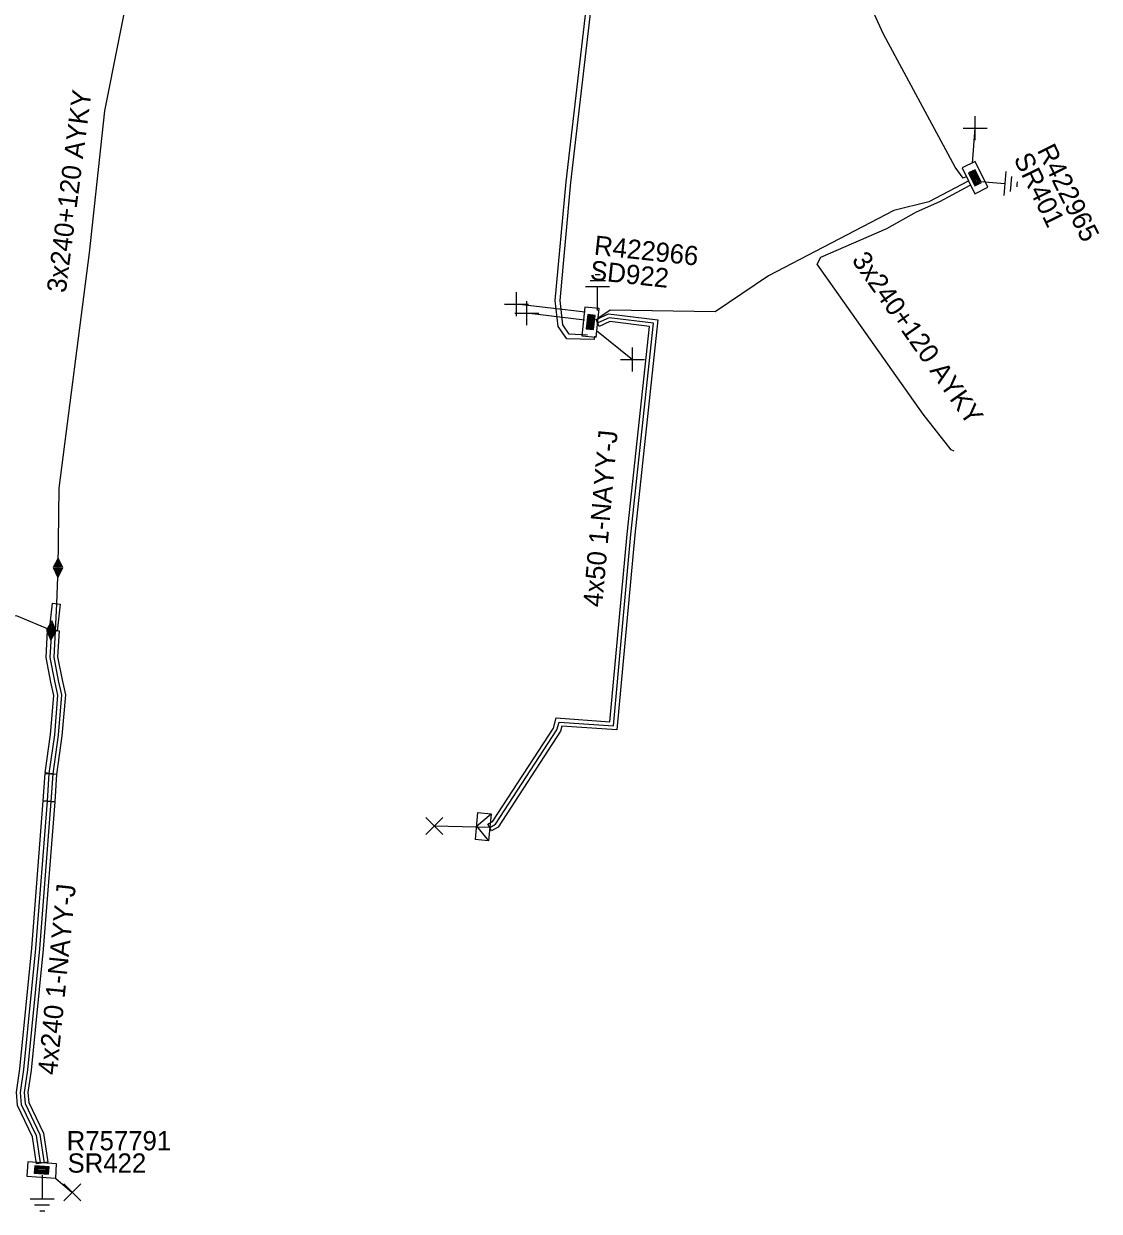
# Model space of a CAD drawing. Extents: x -540466 to -537383, y -1184038 to -1179972.
# Drawn here: x -537936.6 to -537880.7, y -1180884.6 to -1180822.8 of the extents above; entities that cross this region are included whole.
import ezdxf

# ---------------------------------------------------------------- set-up
doc = ezdxf.new("R2010")
doc.units = 0
for name, color, linetype in [('Vrstva 1', 7, 'Continuous'), ('Vrstva 14', 7, 'Continuous'), ('Vrstva 15', 7, 'Continuous'), ('Vrstva 19', 7, 'Continuous'), ('Vrstva 20', 7, 'Continuous'), ('Vrstva 28', 7, 'Continuous'), ('Vrstva 29', 7, 'Continuous'), ('Vrstva 30', 7, 'Continuous'), ('Vrstva 31', 7, 'Continuous'), ('Vrstva 34', 7, 'Continuous'), ('Vrstva 4', 7, 'Continuous'), ('Vrstva 5', 7, 'Continuous'), ('Vrstva 59', 7, 'Continuous'), ('Vrstva 6', 7, 'Continuous'), ('Vrstva 8', 7, 'Continuous'), ('Vrstva 9', 7, 'Continuous')]:
    doc.layers.add(name, color=color, linetype=linetype)

# ---------------------------------------------------------------- blocks, each defined once
blk = doc.blocks.new('NN870')
at = {"layer": 'Vrstva 4'}
for points in [[(0, -0.251), (0.5, 0.001), (0, 0.249), (-0.5, 0.001), (0, -0.251)], [(0.37, -0.003), (0, 0.186), (-0.362, 0.001), (0, -0.188), (0.37, -0.003)], [(0.245, -0.003), (0, 0.123), (-0.252, -0.003), (0, -0.125), (0.245, -0.003)], [(0.122, -0.003), (0, 0.06), (-0.13, -0.003), (0, -0.062), (0.122, -0.003)]]:
    blk.add_lwpolyline(points, dxfattribs=at)
blk = doc.blocks.new('NN800')
at = {"layer": 'Vrstva 1'}
for points in [[(-0.442, 0.442), (0.442, -0.442)], [(-0.442, -0.442), (0.442, 0.442)]]:
    blk.add_lwpolyline(points, dxfattribs=at)
blk = doc.blocks.new('NN620')
at = {"layer": 'Vrstva 8'}
for points in [[(0.752, 0.004), (-0.748, 0.004)], [(-0.748, 0.004), (-0.748, -0.746)], [(0.752, -0.746), (0.752, 0.004)], [(0.368, -0.18), (-0.376, -0.18)], [(-0.376, -0.18), (-0.376, -0.558)], [(-0.376, -0.558), (0.368, -0.558)], [(0.321, -0.227), (-0.329, -0.227)], [(-0.329, -0.227), (-0.329, -0.51)], [(-0.329, -0.51), (0.321, -0.51)], [(0.274, -0.274), (-0.281, -0.274)], [(-0.281, -0.274), (-0.281, -0.463)], [(-0.281, -0.463), (0.274, -0.463)], [(0.227, -0.321), (-0.234, -0.321)], [(-0.234, -0.321), (-0.234, -0.416)], [(-0.234, -0.416), (0.227, -0.416)], [(-0.193, -0.369), (0.185, -0.369)], [(0.227, -0.416), (0.227, -0.321)], [(0.274, -0.463), (0.274, -0.274)], [(0.321, -0.51), (0.321, -0.227)], [(0.368, -0.558), (0.368, -0.18)], [(-0.748, -0.746), (0.752, -0.746)]]:
    blk.add_lwpolyline(points, dxfattribs=at)
blk = doc.blocks.new('NN630')
at = {"layer": 'Vrstva 9'}
for points in [[(-0.003, -0.7), (-0.703, 0)], [(-0.703, -0.7), (-0.703, 0), (0.697, 0), (0.697, -0.7)], [(-0.003, -0.7), (0.697, 0)], [(-0.703, -0.7), (0.697, -0.7)]]:
    blk.add_lwpolyline(points, dxfattribs=at)
blk = doc.blocks.new('NN810')
at = {"layer": 'Vrstva 14'}
for points in [[(0.004, -0.64), (0.004, -1.89)], [(0.629, -1.89), (-0.621, -1.89)], [(0.388, -2.2), (-0.399, -2.2)], [(0.004, -2.515), (-0.124, -2.515)], [(0.137, -2.515), (0.004, -2.515)]]:
    blk.add_lwpolyline(points, dxfattribs=at)

msp = doc.modelspace()

# ---------------------------------------------------------------- linework, layer by layer
at = {"layer": 'Vrstva 20'}
for points in [[(-537912.485, -1180864.435), (-537912.228, -1180864.289), (-537909.081, -1180859.446), (-537908.936, -1180858.918), (-537906.138, -1180859.116), (-537905.246, -1180849.359), (-537904.087, -1180838.573), (-537906.146, -1180838.314), (-537906.695, -1180838.561), (-537906.859, -1180838.197), (-537906.208, -1180837.904), (-537903.647, -1180838.225), (-537904.848, -1180849.399), (-537905.775, -1180859.542), (-537908.637, -1180859.34), (-537908.712, -1180859.612), (-537911.946, -1180864.589), (-537912.288, -1180864.783)], [(-537935.269, -1180854.357), (-537935.109, -1180852.957), (-537934.711, -1180853.003), (-537934.871, -1180854.403)], [(-537935.497, -1180861.779), (-537935.218, -1180859.777), (-537935.053, -1180857.75), (-537935.204, -1180857.05), (-537935.452, -1180855.78), (-537935.369, -1180854.363), (-537934.771, -1180854.397), (-537934.848, -1180855.74), (-537934.616, -1180856.93), (-537934.447, -1180857.71), (-537934.622, -1180859.843), (-537934.903, -1180861.861)], [(-537935.599, -1180863.229), (-537935.499, -1180861.799), (-537934.901, -1180861.841), (-537935.001, -1180863.271)], [(-537935.947, -1180882.095), (-537936.16, -1180880.689), (-537936.934, -1180879.07), (-537936.992, -1180878.381), (-537936.818, -1180877.164), (-537936.189, -1180870.884), (-537935.599, -1180863.227), (-537935.001, -1180863.273), (-537935.591, -1180870.936), (-537936.222, -1180877.236), (-537936.388, -1180878.399), (-537936.346, -1180878.91), (-537935.58, -1180880.511), (-537935.353, -1180882.005)]]:
    msp.add_lwpolyline(points, close=True, dxfattribs=at)
at = {"layer": 'Vrstva 5'}
for points in [[(-537906.939, -1180839.064), (-537906.96, -1180839.242), (-537908.388, -1180839.212), (-537908.831, -1180838.565), (-537908.986, -1180837.211), (-537908.414, -1180831.047), (-537906.276, -1180812.619), (-537906.913, -1180806.391), (-537908.603, -1180799.464), (-537909.424, -1180793.612), (-537909.452, -1180791.998), (-537909.81, -1180788.32), (-537909.74, -1180784.93), (-537909.34, -1180780.41), (-537908.54, -1180775.53), (-537907.694, -1180773.369), (-537905.698, -1180767.309), (-537904.74, -1180764.699), (-537904.48, -1180764.01)], [(-537930.15, -1180818.69), (-537930.052, -1180819.137), (-537930.58, -1180819.63), (-537930.95, -1180820.02), (-537932.42, -1180827.35), (-537933.21, -1180834.74), (-537934.78, -1180846.97), (-537934.83, -1180851.11)], [(-537887.626, -1180830.784), (-537887.777, -1180830.855), (-537888.19, -1180830.28), (-537891.92, -1180823.36), (-537892.98, -1180821.05), (-537893.87, -1180820.57), (-537894.51, -1180820.69), (-537897.84, -1180820.33), (-537901.53, -1180821.1), (-537904.52, -1180821.77), (-537907, -1180821.74), (-537917.93, -1180820.75), (-537927.757, -1180819.88), (-537928.503, -1180819.602), (-537929.58, -1180818.58)], [(-537907.305, -1180839.016), (-537908.252, -1180838.968), (-537908.589, -1180838.475), (-537908.734, -1180837.209), (-537908.166, -1180831.073), (-537906.956, -1180820.652)], [(-537887.519, -1180831.002), (-537889.557, -1180832.078), (-537891.38, -1180832.54), (-537897.89, -1180835.94), (-537900.67, -1180837.81), (-537906.121, -1180837.725), (-537906.772, -1180838.143)], [(-537888.239, -1180845.055), (-537888.409, -1180844.984), (-537889.86, -1180843.13), (-537895.37, -1180835.32), (-537895.18, -1180834.96), (-537891.74, -1180833.47), (-537890.211, -1180832.606), (-537888.995, -1180832.062), (-537887.408, -1180831.226)], [(-537912.387, -1180864.609), (-537912.087, -1180864.439), (-537908.897, -1180859.529), (-537908.787, -1180859.129), (-537905.957, -1180859.329), (-537905.047, -1180849.379), (-537903.867, -1180838.399), (-537906.177, -1180838.109), (-537906.777, -1180838.379)], [(-537934.83, -1180851.11), (-537934.91, -1180852.98), (-537934.97, -1180854.386), (-537935.049, -1180855.753), (-537934.812, -1180856.97), (-537934.649, -1180857.723), (-537934.821, -1180859.821), (-537935.1, -1180861.83), (-537935.2, -1180863.257), (-537935.79, -1180870.919), (-537936.421, -1180877.212), (-537936.589, -1180878.393), (-537936.542, -1180878.963), (-537935.773, -1180880.57), (-537935.548, -1180882.057)], [(-537935.17, -1180854.374), (-537936.98, -1180853.61), (-537941.28, -1180854.35), (-537949.98, -1180854.71), (-537951.472, -1180854.695), (-537960.303, -1180854.845), (-537975.112, -1180855.215), (-537981.461, -1180855.275), (-537989.551, -1180855.315), (-538003.622, -1180855.535), (-538017.592, -1180855.795), (-538031.76, -1180855.995), (-538036.269, -1180855.935), (-538042.769, -1180855.929), (-538043.37, -1180856.26)], [(-537935.17, -1180854.374), (-537935.251, -1180855.767), (-537935.008, -1180857.01), (-537934.851, -1180857.737), (-537935.019, -1180859.799), (-537935.3, -1180861.81), (-537935.4, -1180863.243), (-537935.99, -1180870.901), (-537936.619, -1180877.188), (-537936.791, -1180878.387), (-537936.738, -1180879.017), (-537935.967, -1180880.63), (-537935.752, -1180882.043)]]:
    msp.add_lwpolyline(points, dxfattribs=at)
at = {"layer": 'Vrstva 59'}
for points in [[(-537887.294, -1180830.082), (-537887.154, -1180828.254)], [(-537907.427, -1180837.824), (-537910.991, -1180837.41)], [(-537907.46, -1180838.237), (-537910.462, -1180837.87)], [(-537906.84, -1180838.767), (-537904.973, -1180840.285)], [(-537912.387, -1180864.609), (-537915.265, -1180864.544)], [(-537934.95, -1180882.846), (-537934.086, -1180883.585)]]:
    msp.add_lwpolyline(points, dxfattribs=at)

# ---------------------------------------------------------------- block references
at = {"layer": 'Vrstva 15'}
for p, rotation in [((-537887.497, -1180830.989), 85.63054722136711), ((-537906.777, -1180838.379), 180)]:
    msp.add_blockref('NN810', p, dxfattribs=dict(at, rotation=rotation))
msp.add_blockref('NN810', (-537935.65, -1180882.05), dxfattribs=at)
at = {"layer": 'Vrstva 19'}
for p, rotation in [((-537934.83, -1180851.11), -91.80292309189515), ((-537935.17, -1180854.374), -92.95534730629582)]:
    msp.add_blockref('NN870', p, dxfattribs=dict(at, rotation=rotation))
at = {"layer": 'Vrstva 28'}
for p, rotation in [((-537887.497, -1180830.99), 116.30934993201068), ((-537906.777, -1180838.379), -96.13783611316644), ((-537935.65, -1180882.05), -3.6677879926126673)]:
    msp.add_blockref('NN620', p, dxfattribs=dict(at, rotation=rotation))
at = {"layer": 'Vrstva 31', "rotation": -95.60143336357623}
msp.add_blockref('NN630', (-537912.387, -1180864.609), dxfattribs=at)
at = {"layer": 'Vrstva 34'}
for p, rotation in [((-537887.154, -1180828.254), 45.00000009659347), ((-537910.991, -1180837.41), 45), ((-537910.462, -1180837.87), 45), ((-537904.973, -1180840.285), 45)]:
    msp.add_blockref('NN800', p, dxfattribs=dict(at, rotation=rotation))
for p in [(-537915.265, -1180864.544), (-537934.086, -1180883.585)]:
    msp.add_blockref('NN800', p, dxfattribs=at)

# ---------------------------------------------------------------- texts
at = {"layer": 'Vrstva 29'}
for s, rotation, p in [('R422965', 296.309, (-537883.96, -1180829.395)), ('R422966', 353.862, (-537906.998, -1180834.825))]:
    msp.add_text(s, height=1, rotation=rotation, dxfattribs=at).set_placement(p)
msp.add_text('R757791', height=1, dxfattribs=at).set_placement((-537934.376, -1180881.397))
at = {"layer": 'Vrstva 30'}
for s, rotation, p in [('SR401', 296.309, (-537885.178, -1180829.835)), ('SD922', 353.862, (-537907.205, -1180836.122))]:
    msp.add_text(s, height=1, rotation=rotation, dxfattribs=at).set_placement(p)
msp.add_text('SR422', height=1, dxfattribs=at).set_placement((-537934.332, -1180882.558))
at = {"layer": 'Vrstva 6'}
for s, rotation, p in [('3x240+120 AYKY', 82.685, (-537934.429, -1180836.848)), ('3x240+120 AYKY', 305.203, (-537893.604, -1180835.121)), ('4x50 1-NAYY-J', 84.915, (-537906.546, -1180853.18)), ('4x240 1-NAYY-J', 84.28, (-537934.888, -1180877.509))]:
    msp.add_text(s, height=1, rotation=rotation, dxfattribs=at).set_placement(p)

doc.saveas('drawing.dxf')
